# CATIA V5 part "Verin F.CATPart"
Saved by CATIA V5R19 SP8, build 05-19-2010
Part number: Verin F
Bounding box of the stored display mesh (mm): x 55.688 to 327.395, y 35.003 to 104.997, z -245.667 to -32.278
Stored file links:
  C:\Users\ThinkMotion\Desktop\EU_thinkMotion\iao\IAO_MMS_Groupe3\rdalborgo\rdalborgo\Verin F.CATPart
  C:\Users\ThinkMotion\Desktop\EU_thinkMotion\iao\IAO_MMS_Groupe3\rdalborgo\rdalborgo\rdalborgo.CATProduct
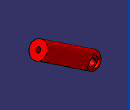
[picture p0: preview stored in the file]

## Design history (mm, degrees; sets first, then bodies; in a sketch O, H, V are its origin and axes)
External parameters (linked from other documents)
  `External.Axe inter diam` = 30 mm
  `External.Axe exter diam` = 50 mm
Set1
  Plane1: linked copy from another document
  Line1: linked copy from another document
  Point1 "D verin": linked copy from another document
  Point2: linked copy from another document
Body1 (main body)
  Sketch1 on Plane1, origin (0, 70, 0), H (-1, 0, 0), V (0, 0, 1)
    line L1 (-124.9615, -183.359) -> (-75.0385, -216.641)
    line L2 (-75.0385, -216.641) -> (-55.624, -187.5192)
    line L3 (-55.624, -187.5192) -> (-288.6299, -32.182)
    line L4 (-288.6299, -32.182) -> (-302.4974, -52.9832)
    line L5 (-302.4974, -52.9832) -> (-294.1769, -58.5302)
    line L6 (-294.1769, -58.5302) -> (-285.8564, -46.0495)
    line L7 (-285.8564, -46.0495) -> (-111.094, -162.5577)
    line L8 (-111.094, -162.5577) -> (-124.9615, -183.359)
    reference projected line E1 (-95.8455, -202.7697) -> (-395.8455, -2.7697) from Line1
    reference projected point E2 (-100, -200) from Point1
    reference projected point E3 (-308.0444, -61.3037) from Point2
    distance L7 L3 = 10
    distance L4 L6 = 10
    distance L8 L2 = 60 {= `External.Axe inter diam` *2}
    distance L5 L1 = 10
    distance L3 L1 = 35
    distance L8 E2 = 30 {= `External.Axe inter diam`}
    perpendicularity: L2 L1
    parallelism: L4 L2
    coincidence: L1 E1, L4 E3
  Shaft1: profile Sketch1, axis Line1, angle 360
  Sketch2 on Plane1, origin (0, 70, 0), H (-1, 0, 0), V (0, 0, 1)
    circle A1 centre (-100, -200) radius 15
    point P1 (-100, -200)
    reference projected point E1 (-100, -200) from Point1
    radius A1 = 15 {= `External.Axe inter diam` /2}
    coincidence: P1 E1
  Pocket1: profile Sketch2, direction (0, -1, 0), through (limit type 3)
  Pocket2: profile Sketch2, direction (0, -1, 0), through (limit type 3)
  Sketch3 on Plane1, origin (0, 70, 0), H (-1, 0, 0), V (0, 0, 1)
    circle A1 centre (-100, -200) radius 25
    point P1 (-100, -200)
    reference projected point E1 (-100, -200) from Point1
    radius A1 = 25 {= `External.Axe exter diam` /2}
    coincidence: P1 E1
  Pocket3: profile Sketch3, direction (0, -1, 0), through (limit type 3), opposite side length -25
  Pocket4: profile Sketch3, direction (0, 1, 0), through (limit type 3), opposite side length -25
